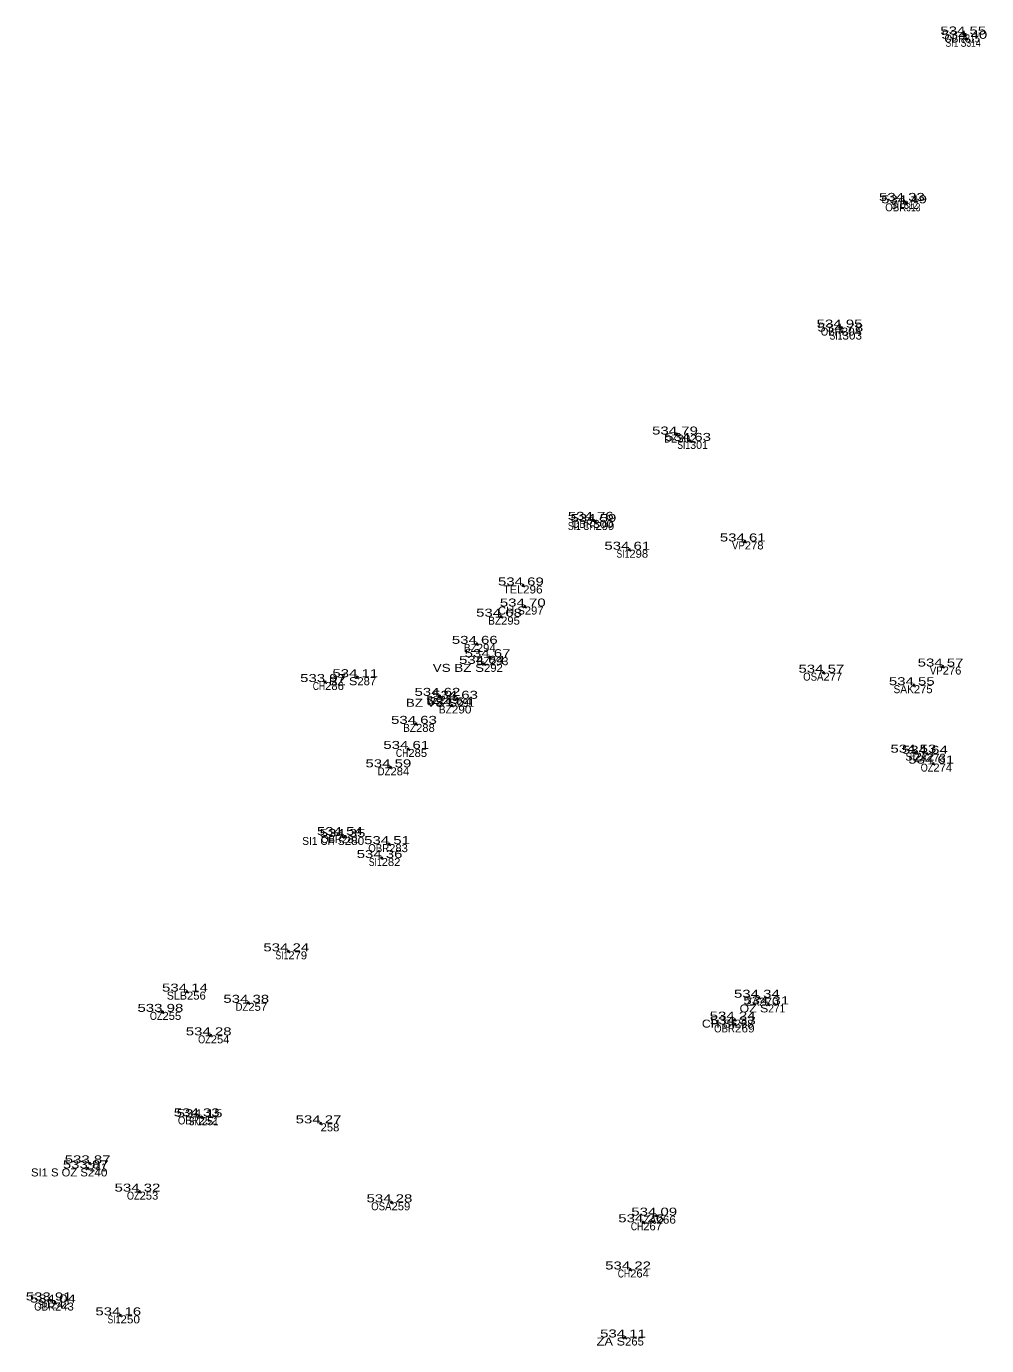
# Model space of a CAD drawing. Extents: x -643086 to -639283, y -1131805 to -1123269.
# Drawn here: x -642922.41 to -642886.4, y -1131300.03 to -1131250.57 of the extents above; entities that cross this region are included whole.
import ezdxf
from ezdxf.enums import TextEntityAlignment as Align

# ---------------------------------------------------------------- set-up
doc = ezdxf.new("R2010")
doc.units = 0
doc.header["$LTSCALE"] = 0.12
doc.header["$PDMODE"] = 32
doc.header["$PDSIZE"] = 0.06
for name, color, linetype in [('1', 7, 'Continuous'), ('2', 7, 'Continuous'), ('3', 7, 'Continuous'), ('4', 7, 'Continuous')]:
    doc.layers.add(name, color=color, linetype=linetype)

msp = doc.modelspace()

# ---------------------------------------------------------------- linework, layer by layer
at = {"layer": '1'}
for p in [(-642887.2, -1131250.87), (-642887.16, -1131251.03), (-642889.5, -1131257.11), (-642889.42, -1131257.2), (-642891.84, -1131261.86), (-642891.81, -1131262.01), (-642898.01, -1131265.87), (-642897.52, -1131266.11), (-642901.17, -1131269.07), (-642901.07, -1131269.15), (-642899.8, -1131270.19), (-642895.47, -1131269.88), (-642903.79, -1131271.53), (-642904.61, -1131272.7), (-642903.72, -1131272.32), (-642905.52, -1131273.72), (-642905.25, -1131274.47), (-642905.04, -1131274.22), (-642888.05, -1131274.57), (-642911.21, -1131275.15), (-642910, -1131274.97), (-642892.52, -1131274.8), (-642906.92, -1131275.67), (-642889.13, -1131275.27), (-642906.46, -1131276.03), (-642906.26, -1131275.78), (-642907.8, -1131276.72), (-642908.09, -1131277.66), (-642889.07, -1131277.8), (-642888.64, -1131277.84), (-642908.76, -1131278.35), (-642888.4, -1131278.21), (-642910.58, -1131280.89), (-642910.48, -1131280.96), (-642908.81, -1131281.23), (-642909.09, -1131281.75), (-642912.59, -1131285.25), (-642916.39, -1131286.76), (-642894.94, -1131286.99), (-642917.31, -1131287.52), (-642914.09, -1131287.18), (-642894.59, -1131287.24), (-642895.85, -1131287.81), (-642895.84, -1131287.99), (-642915.5, -1131288.4), (-642915.95, -1131291.44), (-642915.84, -1131291.47), (-642911.38, -1131291.7), (-642920.11, -1131293.39), (-642920.04, -1131293.2), (-642918.17, -1131294.26), (-642908.72, -1131294.66), (-642899.28, -1131295.41), (-642898.79, -1131295.16), (-642899.77, -1131297.18), (-642921.5, -1131298.34), (-642921.34, -1131298.42), (-642918.89, -1131298.9), (-642899.96, -1131299.73)]:
    msp.add_point(p, dxfattribs=at)

# ---------------------------------------------------------------- texts
at = {"layer": '2'}
for s, width, p in [('315', 0.8, (-642887.2, -1131251.17)), ('314', 0.8, (-642887.16, -1131251.33)), ('312', 0.8, (-642889.5, -1131257.41)), ('313', 0.8, (-642889.42, -1131257.5)), ('304', 1.1, (-642891.84, -1131262.16)), ('303', 1.1, (-642891.81, -1131262.31)), ('302', 1.1, (-642898.01, -1131266.17)), ('300', 1.15, (-642901.17, -1131269.37)), ('299', 1.05, (-642901.07, -1131269.45)), ('298', 1.05, (-642899.8, -1131270.49)), ('278', 1.05, (-642895.47, -1131270.18)), ('296', 1.1, (-642903.79, -1131271.83)), ('297', 1.05, (-642903.72, -1131272.62)), ('295', 1.05, (-642904.61, -1131273)), ('294', 1.05, (-642905.52, -1131274.02)), ('292', 1.05, (-642905.25, -1131274.77)), ('293', 1.05, (-642905.04, -1131274.52)), ('276', 1.05, (-642888.05, -1131274.87)), ('286', 1.05, (-642911.21, -1131275.45)), ('287', 1.05, (-642910, -1131275.27)), ('277', 1.05, (-642892.52, -1131275.1)), ('275', 1.05, (-642889.13, -1131275.57)), ('289', 1.05, (-642906.92, -1131275.97)), ('290', 1.1, (-642906.46, -1131276.33)), ('291', 0.95, (-642906.26, -1131276.08)), ('288', 1.05, (-642907.8, -1131277.02)), ('285', 1.05, (-642908.09, -1131277.96)), ('272', 1.05, (-642889.07, -1131278.1)), ('273', 1.05, (-642888.64, -1131278.14)), ('284', 1.05, (-642908.76, -1131278.65)), ('274', 1.05, (-642888.4, -1131278.51)), ('281', 0.95, (-642910.58, -1131281.19)), ('280', 1.1, (-642910.48, -1131281.26)), ('283', 1.05, (-642908.81, -1131281.53)), ('282', 1.05, (-642909.09, -1131282.05)), ('279', 1.05, (-642912.59, -1131285.55)), ('256', 1.05, (-642916.39, -1131287.06)), ('270', 1.1, (-642894.94, -1131287.29)), ('257', 1.05, (-642914.09, -1131287.48)), ('271', 0.95, (-642894.59, -1131287.54)), ('255', 1.05, (-642917.31, -1131287.82)), ('268', 1.05, (-642895.85, -1131288.11)), ('269', 1.1, (-642895.84, -1131288.29)), ('254', 1.05, (-642915.5, -1131288.7)), ('252', 1.05, (-642915.95, -1131291.74)), ('251', 0.95, (-642915.84, -1131291.77)), ('258', 1.05, (-642911.38, -1131292)), ('240', 1.1, (-642920.11, -1131293.69)), ('241', 0.95, (-642920.04, -1131293.5)), ('253', 1.05, (-642918.17, -1131294.56)), ('259', 1.05, (-642908.72, -1131294.96)), ('267', 1.05, (-642899.28, -1131295.71)), ('266', 1.1, (-642898.79, -1131295.46)), ('264', 1.05, (-642899.77, -1131297.48)), ('242', 1.05, (-642921.5, -1131298.64)), ('243', 1.05, (-642921.34, -1131298.72)), ('250', 1.1, (-642918.89, -1131299.2)), ('265', 1.05, (-642899.96, -1131300.03))]:
    msp.add_text(s, height=0.3, dxfattribs=dict(at, width=width)).set_placement(p)
msp.add_text('301', height=0.3, dxfattribs=at).set_placement((-642897.52, -1131266.41))
at = {"layer": '3', "width": 1.4}
for s, p in [('534 55 ', (-642887.2, -1131250.87)), ('534 40 ', (-642887.16, -1131251.03)), ('534 33 ', (-642889.5, -1131257.11)), ('534 49 ', (-642889.42, -1131257.2)), ('534 95 ', (-642891.84, -1131261.86)), ('534 78 ', (-642891.81, -1131262.01)), ('534 79 ', (-642898.01, -1131265.87)), ('534 63 ', (-642897.52, -1131266.11)), ('534 76 ', (-642901.17, -1131269.07)), ('534 59 ', (-642901.07, -1131269.15)), ('534 61 ', (-642895.47, -1131269.88)), ('534 61 ', (-642899.8, -1131270.19)), ('534 69 ', (-642903.79, -1131271.53)), ('534 70 ', (-642903.72, -1131272.32)), ('534 68 ', (-642904.61, -1131272.7)), ('534 66 ', (-642905.52, -1131273.72)), ('534 67 ', (-642905.04, -1131274.22)), ('534 64 ', (-642905.25, -1131274.47)), ('534 57 ', (-642892.52, -1131274.8)), ('534 57 ', (-642888.05, -1131274.57)), ('533 97 ', (-642911.21, -1131275.15)), ('534 11 ', (-642910, -1131274.97)), ('534 55 ', (-642889.13, -1131275.27)), ('534 62 ', (-642906.92, -1131275.67)), ('534 63 ', (-642906.26, -1131275.78)), ('534 64 ', (-642906.46, -1131276.03)), ('534 63 ', (-642907.8, -1131276.72)), ('534 61 ', (-642908.09, -1131277.66)), ('534 53 ', (-642889.07, -1131277.8)), ('534 64 ', (-642888.64, -1131277.84)), ('534 59 ', (-642908.76, -1131278.35)), ('534 61 ', (-642888.4, -1131278.21)), ('534 54 ', (-642910.58, -1131280.89)), ('534 35 ', (-642910.48, -1131280.96)), ('534 51 ', (-642908.81, -1131281.23)), ('534 36 ', (-642909.09, -1131281.75)), ('534 24 ', (-642912.59, -1131285.25)), ('534 14 ', (-642916.39, -1131286.76)), ('534 38 ', (-642914.09, -1131287.18)), ('534 34 ', (-642894.94, -1131286.99)), ('534 31 ', (-642894.59, -1131287.24)), ('533 98 ', (-642917.31, -1131287.52)), ('534 24 ', (-642895.85, -1131287.81)), ('534 33 ', (-642895.84, -1131287.99)), ('534 28 ', (-642915.5, -1131288.4)), ('534 33 ', (-642915.95, -1131291.44)), ('534 15 ', (-642915.84, -1131291.47)), ('534 27 ', (-642911.38, -1131291.7)), ('533 87 ', (-642920.04, -1131293.2)), ('533 87 ', (-642920.11, -1131293.39)), ('534 32 ', (-642918.17, -1131294.26)), ('534 28 ', (-642908.72, -1131294.66)), ('534 09 ', (-642898.79, -1131295.16)), ('534 26 ', (-642899.28, -1131295.41)), ('534 22 ', (-642899.77, -1131297.18)), ('533 91 ', (-642921.5, -1131298.34)), ('534 04 ', (-642921.34, -1131298.42)), ('534 16 ', (-642918.89, -1131298.9)), ('534 11 ', (-642899.96, -1131299.73))]:
    msp.add_text(s, height=0.3, dxfattribs=at).set_placement(p, align=Align.CENTER)
at = {"layer": '4'}
for s, width, p in [('OBR', 0.9, (-642887.2, -1131251.17)), ('SI1 S', 0.8, (-642887.16, -1131251.33)), ('OBR', 0.9, (-642889.42, -1131257.5)), ('SI1', 0.8, (-642889.5, -1131257.41)), ('OBR', 0.9, (-642891.84, -1131262.16)), ('SI1', 0.8, (-642891.81, -1131262.31)), ('DZ', 0.9, (-642898.01, -1131266.17)), ('SI1', 0.8, (-642897.52, -1131266.41)), ('SI1 CH', 0.8, (-642901.07, -1131269.45)), ('OBR', 0.9, (-642901.17, -1131269.37)), ('SI1', 0.8, (-642899.8, -1131270.49)), ('VP', 0.9, (-642895.47, -1131270.18)), ('CH S', 1.05, (-642903.72, -1131272.62)), ('BZ', 0.95, (-642904.61, -1131273)), ('BZ', 0.95, (-642905.52, -1131274.02)), ('VS BZ S', 1.25, (-642905.25, -1131274.77)), ('BZ', 0.95, (-642905.04, -1131274.52)), ('VP', 0.9, (-642888.05, -1131274.87)), ('CH', 0.8, (-642911.21, -1131275.45)), ('BZ S', 1.2, (-642910, -1131275.27)), ('OSA', 0.9, (-642892.52, -1131275.1)), ('SAK', 0.95, (-642889.13, -1131275.57)), ('BZ VS S', 1.25, (-642906.26, -1131276.08)), ('BZ', 0.95, (-642906.92, -1131275.97)), ('BZ', 0.95, (-642906.46, -1131276.33)), ('BZ', 0.95, (-642907.8, -1131277.02)), ('CH', 0.8, (-642908.09, -1131277.96)), ('ZA', 0.95, (-642888.64, -1131278.14)), ('DZ', 0.9, (-642908.76, -1131278.65)), ('OZ', 0.85, (-642888.4, -1131278.51)), ('SI1 CH S', 0.95, (-642910.48, -1131281.26)), ('OBR', 0.9, (-642910.58, -1131281.19)), ('OBR', 0.9, (-642908.81, -1131281.53)), ('SI1', 0.8, (-642909.09, -1131282.05)), ('SI1', 0.8, (-642912.59, -1131285.55)), ('ZA', 0.95, (-642894.94, -1131287.29)), ('DZ', 0.9, (-642914.09, -1131287.48)), ('OZ S', 1.15, (-642894.59, -1131287.54)), ('OZ', 0.85, (-642917.31, -1131287.82)), ('CH SI', 1.15, (-642895.85, -1131288.11)), ('OBR', 0.9, (-642895.84, -1131288.29)), ('OZ', 0.85, (-642915.5, -1131288.7)), ('OBR', 0.9, (-642915.95, -1131291.74)), ('SI1', 0.8, (-642915.84, -1131291.77)), ('SI1 S OZ S', 1.05, (-642920.11, -1131293.69)), ('OZ', 0.85, (-642918.17, -1131294.56)), ('OSA', 0.9, (-642908.72, -1131294.96)), ('CH', 0.8, (-642899.28, -1131295.71)), ('ZA', 0.95, (-642898.79, -1131295.46)), ('CH', 0.8, (-642899.77, -1131297.48)), ('SI1', 0.8, (-642921.5, -1131298.64)), ('OBR', 0.9, (-642921.34, -1131298.72)), ('SI1', 0.8, (-642918.89, -1131299.2)), ('ZA S', 1.2, (-642899.96, -1131300.03))]:
    msp.add_text(s, height=0.3, dxfattribs=dict(at, width=width)).set_placement(p, align=Align.RIGHT)
for s, p in [('TEL', (-642903.79, -1131271.83)), ('SI', (-642889.07, -1131278.1)), ('SLB', (-642916.39, -1131287.06))]:
    msp.add_text(s, height=0.3, dxfattribs=at).set_placement(p, align=Align.RIGHT)

doc.saveas('drawing.dxf')
